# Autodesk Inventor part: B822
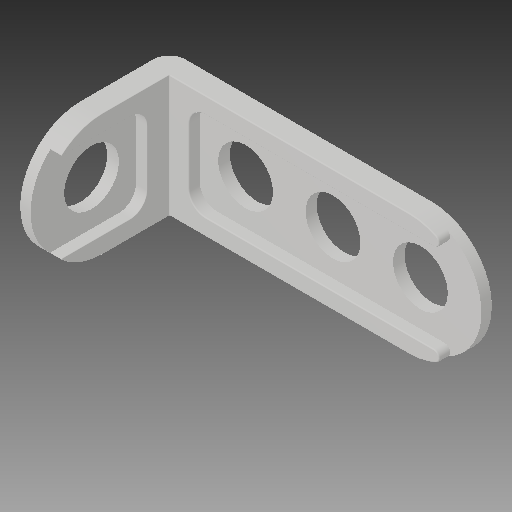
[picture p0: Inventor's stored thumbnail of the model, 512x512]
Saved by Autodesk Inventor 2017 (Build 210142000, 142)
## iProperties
Part Number: B822
Material: Générique
Document SubType Name: Modeling
Designer: ficho
Density: 1 g/cm^3
Appearance: Par défaut
Author: ficho
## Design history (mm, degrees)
feature "Solid1"
node "Solide1"
